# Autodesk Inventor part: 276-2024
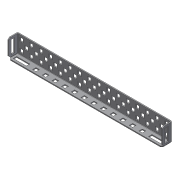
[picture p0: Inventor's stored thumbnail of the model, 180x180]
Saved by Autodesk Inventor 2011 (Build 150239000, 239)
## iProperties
Company: Autodesk Inc.
Created: 2005-08
Part Number: 276-2024
Document SubType Name: Sheet Metal
Designer: Autodesk Inc.
Density: 1 g/cm^3
Sheet Metal Rule: Default
Catalog Web Link: http://www.vexrobotics.com/products/accessories/structure/chassis-kit.html
Description: This rail has holes on 0.500" increments and another row in-between. This part is an angle with one narrow and one taller side.
Vendor: Innovation First, Inc.
Author: Autodesk Inc.
Title: VEX Robotics Kit of Parts
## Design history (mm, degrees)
node "Face1"
  sketch "Sketch1"
    geometry: L1 (-100.33, 22.86)-(100.33, 22.86); L2 (-97.536, 19.939)-(-92.964, 19.939); L3 (-92.964, 19.939)-(-92.964, 15.367); L4 (-92.964, 15.367)-(-97.536, 15.367); L5 (-97.536, 15.367)-(-97.536, 19.939); L6 (-97.536, 7.239)-(-92.964, 7.239); L7 (-92.964, 7.239)-(-92.964, 2.667); L8 (-92.964, 2.667)-(-97.536, 2.667); L9 (-97.536, 2.667)-(-97.536, 7.239); L10 (-84.836, 19.939)-(-80.264, 19.939); L11 (-80.264, 19.939)-(-80.264, 15.367); L12 (-80.264, 15.367)-(-84.836, 15.367); L13 (-84.836, 15.367)-(-84.836, 19.939); L14 (-84.836, 7.239)-(-80.264, 7.239); L15 (-80.264, 7.239)-(-80.264, 2.667); L16 (-80.264, 2.667)-(-84.836, 2.667); L17 (-84.836, 2.667)-(-84.836, 7.239); L18 (-91.186, 9.017)-(-91.186, 13.589); L19 (-91.186, 13.589)-(-86.614, 13.589); L20 (-86.614, 9.017)-(-91.186, 9.017); L21 (-86.614, 13.589)-(-86.614, 9.017); L22 (-78.486, 9.017)-(-78.486, 13.589); L23 (-73.914, 9.017)-(-78.486, 9.017); L24 (-78.486, 13.589)-(-73.914, 13.589); L25 (-73.914, 13.589)-(-73.914, 9.017); L26 (-72.136, 15.367)-(-72.136, 19.939); L27 (-72.136, 2.667)-(-72.136, 7.239); L28 (-67.564, 2.667)-(-72.136, 2.667); L29 (-67.564, 7.239)-(-67.564, 2.667); L30 (-72.136, 7.239)-(-67.564, 7.239); L31 (-67.564, 15.367)-(-72.136, 15.367); L32 (-72.136, 19.939)-(-67.564, 19.939); L33 (-67.564, 19.939)-(-67.564, 15.367); L34 (-65.786, 9.017)-(-65.786, 13.589); L35 (-61.214, 9.017)-(-65.786, 9.017); L36 (-65.786, 13.589)-(-61.214, 13.589); L37 (-61.214, 13.589)-(-61.214, 9.017); L38 (-59.436, 15.367)-(-59.436, 19.939); L39 (-59.436, 2.667)-(-59.436, 7.239); L40 (-54.864, 2.667)-(-59.436, 2.667); L41 (-54.864, 7.239)-(-54.864, 2.667); L42 (-59.436, 7.239)-(-54.864, 7.239); L43 (-54.864, 15.367)-(-59.436, 15.367); L44 (-59.436, 19.939)-(-54.864, 19.939); L45 (-54.864, 19.939)-(-54.864, 15.367); L46 (-53.086, 9.017)-(-53.086, 13.589); L47 (-48.514, 9.017)-(-53.086, 9.017); L48 (-53.086, 13.589)-(-48.514, 13.589); L49 (-48.514, 13.589)-(-48.514, 9.017); L50 (-46.736, 15.367)-(-46.736, 19.939); L51 (-46.736, 2.667)-(-46.736, 7.239); L52 (-42.164, 2.667)-(-46.736, 2.667); L53 (-42.164, 7.239)-(-42.164, 2.667); L54 (-46.736, 7.239)-(-42.164, 7.239); L55 (-42.164, 15.367)-(-46.736, 15.367); L56 (-46.736, 19.939)-(-42.164, 19.939); L57 (-42.164, 19.939)-(-42.164, 15.367); L58 (-40.386, 9.017)-(-40.386, 13.589); L59 (-35.814, 9.017)-(-40.386, 9.017); L60 (-40.386, 13.589)-(-35.814, 13.589); L61 (-35.814, 13.589)-(-35.814, 9.017); L62 (-34.036, 15.367)-(-34.036, 19.939); L63 (-34.036, 2.667)-(-34.036, 7.239); L64 (-29.464, 2.667)-(-34.036, 2.667)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; 2 further points
    constraints: 384 end point, 12 parallel, 8 collinear, 7 horizontal, 6 perpendicular, 1 coincident, 1 midpoint, 336 other
    dimensions: "d20" = 2.794 distance between parallel lines of L192 L5; "d21" = 2.794 distance between parallel lines of L190 L189; "d22" = 2.921 distance between parallel lines of L1 L2; "d23" = 22.86 distance between parallel lines of L191 L1; "d24" = 4.572 distance of L4.end L2.start; "d25" = 8.128 distance between parallel lines of L6 L4; "d26" = 4.572 distance of L8.end L6.start; "d125" = 200.66 distance of L190.end L191.end; "d126" = 4.572 distance of L2.start L2.end; "d127" = 4.572 distance of L18.end L19.end; "d128" = 4.572 distance of L19.end L20.start; "d129" = 9.017 distance between parallel lines of L191 L20; "d130" = 9.144 distance between parallel lines of L192 L18; "d131" = 7.366 distance between parallel lines of L183 L190; "d132" = 9.144 distance between parallel lines of L181 L190
node "Flange5"
node "Flange6"
feature "Corner Chamfer2" dims "d84" = 1.905, "d85" = 6.35, angle "d86" = 45 deg
node "Flange7"
sketch "Sketch11" dims "d99" = 25.4
  geometry: L1 (200.279, -9.246)-(200.279, 0) reference; L2 (-0.381, 0)-(-0.381, -9.246) reference; L3 (1.524, -11.151)-(198.374, -11.151) reference; L4 (2.413, -3.785)-(19.685, -3.785); L5 (19.685, -3.785)-(19.685, -8.357); L6 (19.685, -8.357)-(2.413, -8.357); L7 (2.413, -8.357)-(2.413, -3.785); L8 (27.813, -3.785)-(32.385, -3.785); L9 (32.385, -3.785)-(32.385, -8.357); L10 (32.385, -8.357)-(27.813, -8.357); L11 (27.813, -8.357)-(27.813, -3.785); L12 (40.513, -8.357)-(40.513, -3.785); L13 (45.085, -8.357)-(40.513, -8.357); L14 (45.085, -3.785)-(45.085, -8.357); L15 (40.513, -3.785)-(45.085, -3.785); L16 (53.213, -8.357)-(53.213, -3.785); L17 (57.785, -8.357)-(53.213, -8.357); L18 (57.785, -3.785)-(57.785, -8.357); L19 (53.213, -3.785)-(57.785, -3.785); L20 (65.913, -8.357)-(65.913, -3.785); L21 (70.485, -8.357)-(65.913, -8.357); L22 (70.485, -3.785)-(70.485, -8.357); L23 (65.913, -3.785)-(70.485, -3.785); L24 (78.613, -8.357)-(78.613, -3.785); L25 (83.185, -8.357)-(78.613, -8.357); L26 (83.185, -3.785)-(83.185, -8.357); L27 (78.613, -3.785)-(83.185, -3.785); L28 (91.313, -8.357)-(91.313, -3.785); L29 (95.885, -8.357)-(91.313, -8.357); L30 (95.885, -3.785)-(95.885, -8.357); L31 (91.313, -3.785)-(95.885, -3.785); L32 (104.013, -8.357)-(104.013, -3.785); L33 (108.585, -8.357)-(104.013, -8.357); L34 (108.585, -3.785)-(108.585, -8.357); L35 (104.013, -3.785)-(108.585, -3.785); L36 (116.713, -8.357)-(116.713, -3.785); L37 (121.285, -8.357)-(116.713, -8.357); L38 (121.285, -3.785)-(121.285, -8.357); L39 (116.713, -3.785)-(121.285, -3.785); L40 (129.413, -8.357)-(129.413, -3.785); L41 (133.985, -8.357)-(129.413, -8.357); L42 (133.985, -3.785)-(133.985, -8.357); L43 (129.413, -3.785)-(133.985, -3.785); L44 (142.113, -8.357)-(142.113, -3.785); L45 (146.685, -8.357)-(142.113, -8.357); L46 (146.685, -3.785)-(146.685, -8.357); L47 (142.113, -3.785)-(146.685, -3.785); L48 (154.813, -8.357)-(154.813, -3.785); L49 (159.385, -8.357)-(154.813, -8.357); L50 (159.385, -3.785)-(159.385, -8.357); L51 (154.813, -3.785)-(159.385, -3.785); L52 (167.513, -8.357)-(167.513, -3.785); L53 (172.085, -8.357)-(167.513, -8.357); L54 (172.085, -3.785)-(172.085, -8.357); L55 (167.513, -3.785)-(172.085, -3.785); L56 (180.213, -3.785)-(197.485, -3.785); L57 (197.485, -3.785)-(197.485, -8.357); L58 (197.485, -8.357)-(180.213, -8.357); L59 (180.213, -8.357)-(180.213, -3.785)
  constraints: 112 end point, 6 parallel, 4 horizontal, 3 perpendicular, 2 collinear, 88 other
  dimensions: "d88" = 17.272 distance between parallel lines of L5 L7; "d89" = 2.794 distance between parallel lines of L3 L6; "d90" = 2.794 distance between parallel lines of L2 L7; "d91" = 4.572 distance between parallel lines of L4 L6; "d92" = 4.572 distance between parallel lines of L9 L11; "d93" = 8.128 distance between parallel lines of L11 L5; "d96" = 12.7 distance of L10.end L12.start; "d102" = 8.128 distance between parallel lines of L54 L59; "d103" = 2.794 distance between parallel lines of L1 L57; "d111" = 4.572 distance between parallel lines of L56 L58; "d112" = 2.794 distance between parallel lines of L3 L58
cut "Cut2" sketch "Sketch11" dims "d113" = 1.27 (= Thickness), "d114" = 0
feature "Corner Chamfer3" dims "d115" = 1.905, "d116" = 6.35, angle "d117" = 45 deg
sketch "Sketch13"
  geometry: L1 (-9.246, 22.479)-(0, 22.479) reference; L2 (-11.151, 1.905)-(-11.151, 20.574) reference; L3 (-8.357, 19.685)-(-3.785, 19.685); L4 (-3.785, 19.685)-(-3.785, 2.413); L5 (-3.785, 2.413)-(-8.357, 2.413); L6 (-8.357, 2.413)-(-8.357, 19.685)
  constraints: 8 end point, 2 parallel, 1 horizontal, 1 perpendicular
  dimensions: "d118" = 2.794 distance between parallel lines of L2 L6; "d119" = 2.794 distance between parallel lines of L3 L1; "d121" = 17.272 distance of L5.end L3.start; "d122" = 4.572 distance of L3.start L3.end
cut "Cut3" sketch "Sketch13" dims "d123" = 1.27 (= Thickness), "d124" = 0
body "Solid1"
face "Plate1" dims "Thickness" = 1.27
sketch "Sketch7"
  geometry: L1 (200.66, 0)-(200.66, 11.532); L2 (200.66, 11.532)-(0, 11.532); 2 other entities
  constraints: 4 end point, 4 other
face "Plate6" dims "d64" = 1.27 (= BendReliefWidth), "d66" = 2.54 (= MinimumRemnant), "d68" = 11.5316, "d69" = 90 deg, "d70" = 0.381 (= BendRadius), "Thickness" = 1.27
bend "Bend5" dims "d64" = 1.27 (= BendReliefWidth), "d65" = 0.635 (= BendReliefDepth), "d66" = 2.54 (= MinimumRemnant), "d67" = 0.381 (= BendRadius), "d68" = 11.5316, "d69" = 90 deg, "d70" = 0.381 (= BendRadius), "SeamGap" = 0.00508, "Thickness" = 1.27
sketch "Sketch8"
  geometry: L1 (22.479, 0)-(22.479, 11.532); L2 (22.479, 11.532)-(0, 11.532); 2 other entities
  constraints: 4 end point, 4 other
face "Plate7" dims "d71" = 1.27 (= BendReliefWidth), "d73" = 2.54 (= MinimumRemnant), "d75" = 11.5316, "d76" = 90 deg, "d77" = 0.381 (= BendRadius), "Thickness" = 1.27
bend "Bend6" dims "d71" = 1.27 (= BendReliefWidth), "d72" = 0.635 (= BendReliefDepth), "d73" = 2.54 (= MinimumRemnant), "d74" = 0.381 (= BendRadius), "d75" = 11.5316, "d76" = 90 deg, "d77" = 0.381 (= BendRadius), "SeamGap" = 0.00508, "Thickness" = 1.27
sketch "Sketch12"
  geometry: L1 (22.479, 0)-(22.479, 11.532); L2 (22.479, 11.532)-(0, 11.532); 2 other entities
  constraints: 4 end point, 4 other
face "Plate8" dims "d104" = 1.27 (= BendReliefWidth), "d106" = 2.54 (= MinimumRemnant), "d108" = 11.5316, "d109" = 90 deg, "d110" = 0.381 (= BendRadius), "Thickness" = 1.27
bend "Bend7" dims "d104" = 1.27 (= BendReliefWidth), "d105" = 0.635 (= BendReliefDepth), "d106" = 2.54 (= MinimumRemnant), "d107" = 0.381 (= BendRadius), "d108" = 11.5316, "d109" = 90 deg, "d110" = 0.381 (= BendRadius), "SeamGap" = 0.00508, "Thickness" = 1.27
other parameters: "BendRadius" = 0.381, "BendReliefWidth" = 1.27 (= Thickness), "BendReliefDepth" = 0.635 (= 0.5 x Thickness), "CornerReliefSize" = 5.08 (= 4 x Thickness), "MinimumRemnant" = 2.54 (= 2 x Thickness), "TransitionRadius" = 0.381 (= BendRadius), "d13" = 12.7, "d16" = 25.4, "d27" = 0.381 (= BendRadius), "JacobiRadiusSize" = 1.27 (= Thickness), "GapSize" = 1.27 (= Thickness)
